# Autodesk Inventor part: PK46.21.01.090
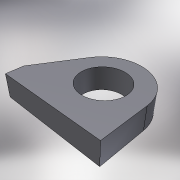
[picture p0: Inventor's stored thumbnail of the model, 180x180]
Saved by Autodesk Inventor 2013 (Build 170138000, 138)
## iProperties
Created: 2005-04
Part Number: PK46.21.01.090
Material: Steel, Mild
Document SubType Name: Modeling
Designer: salex
Manufacturer: Standard
Standards Organization: Custom
Density: 7.86 g/cm^3
Author: salex
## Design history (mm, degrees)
sketch "Эскиз1"
  geometry: L1 (275.476, 609.23)-(185.476, 609.23); L2 (185.476, 609.23)-(185.476, 624.23); L3 (185.476, 624.23)-(210.212, 666.811); L4 (275.476, 649.23)-(275.476, 609.23); C1 r 20 at (240.476, 649.23); A1 r 35 centre (240.476, 649.23) between (275.476, 649.23) and (210.212, 666.811)
  constraints: 8 end point, 2 centre point, 2 point on circle, 2 tangent, 1 concentric, 1 horizontal, 1 parallel, 1 perpendicular, 1 other
  dimensions: "d0" = 15 distance from line of L2.end L1; "d1" = 90 distance of L1.start L1.end; "d2" = 40 distance from line of C1.centre L1; "d3" = 40 diameter of C1; "d4" = 35 radius of A1
extrude "Выдавливание1" new body sketch "Эскиз1" distance "d6" = 20; taper "d7" = 0 deg
body "Solid1"
